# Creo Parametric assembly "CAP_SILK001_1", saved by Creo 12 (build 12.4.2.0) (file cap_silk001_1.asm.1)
Units: Custom; MM, KILOGRAM, SECS

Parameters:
  PTC_WM_ITERATION = "0"
  PTC_WM_VERSION = "-.0"
  PTC_WM_LIFECYCLE_STATE = "In Work"
  PTC_WM_LIFECYCLE = "MO_CADDocument"
  PTC_WM_CREATED_BY = "Maximilian Roepper (Z0017RMS: MO)"
  PTC_WM_CREATED_ON = "18-Sep-26 11:36:42 AM"
  PTC_WM_MODIFIED_BY = "Maximilian Roepper (Z0017RMS: MO)"
  PTC_WM_MODIFIED_ON = "18-Sep-26 11:36:46 AM"
  PDMLINKNUMBER = "PDM000071455217"
  PTC_WM_NAME = "cap_silk001_1.asm"
  PTC_WM_NUMBER = "PDM000071455217"

Other parameters: WEIGHT, WEIGHT_FACTOR, WEIGHT_ADD, MC_ERRORS, SUPPLIER, ISPOSITIONINGASSEMBLY

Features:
  1. coordinate system
  2. imported feature
  3. component "CAP_SILK_UP_1"
  4. component "CAP_SILK_DWN_1"

Other named items: DRW_VIEW_ORG, ROUGH-GROB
